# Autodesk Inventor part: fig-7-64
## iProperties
Shininess: 64.0
Length Units: 11269
Angle Units: 11279
Time Units: 11290
Mass Units: 11283
Length Display Precision: 3
Angle Display Precision: 2
Compacted: True
Part Number: fig-7-64
Document SubType Name: Modeling
Created: 2002-12
Designer: deepak
Density: 1 g/cm^3
Density: 0.0
Volumn: 0.0
Area: 0.0
PropertySet Name: Model Information
Control State: 0
Master: False
Checked Out: False
Author: deepak
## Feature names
1. Extrusion1
2. Split1
